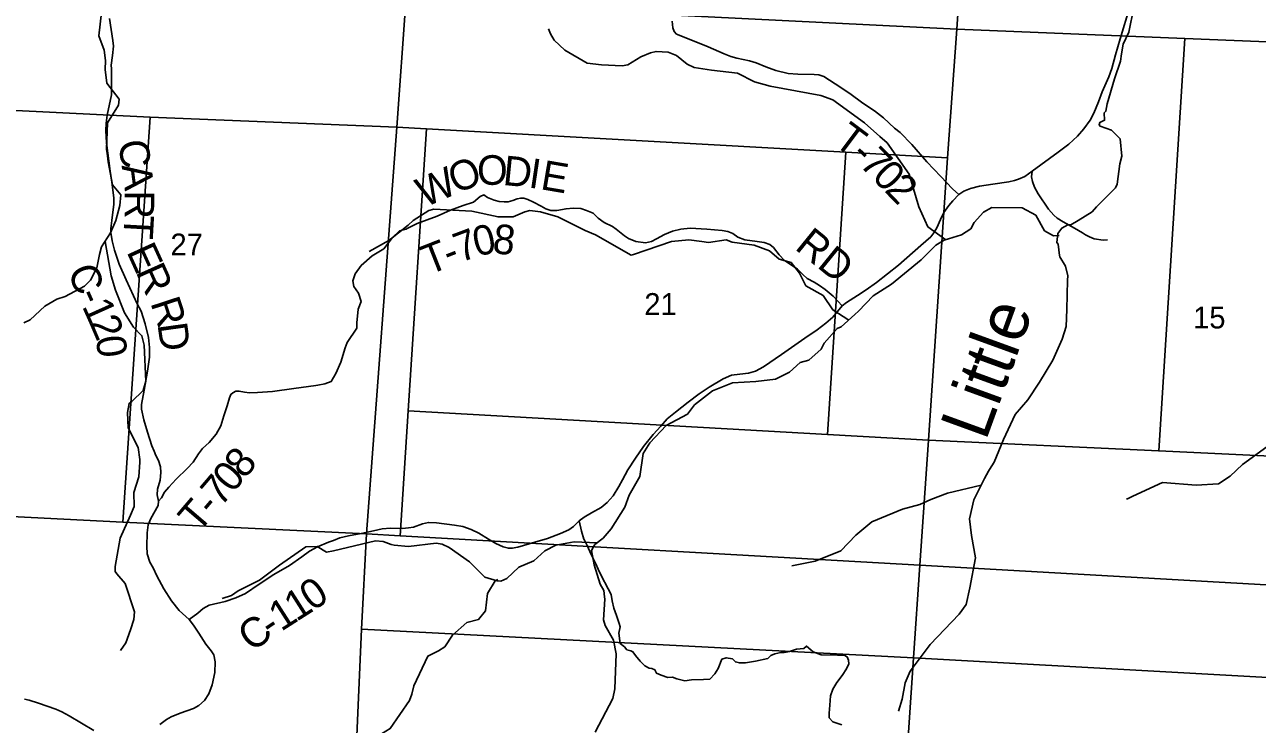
# Model space of a CAD drawing. Extents: x 1878108 to 2183446, y 146837 to 508383.
# Drawn here: x 2017962 to 2030457, y 254185 to 261280 of the extents above; entities that cross this region are included whole.
import ezdxf

# ---------------------------------------------------------------- set-up
doc = ezdxf.new("R2010")
doc.units = 0
for name, color, linetype in [('GM_X_County_Road', 7, 'Continuous'), ('GM_X_County_Road_Text', 7, 'Continuous'), ('GM_X_Minor_River', 7, 'Continuous'), ('GM_X_Minor_River_Text', 7, 'Continuous'), ('GM_X_Section', 7, 'Continuous'), ('GM_X_Section_Text', 7, 'Continuous'), ('GM_X_Township_Road', 7, 'Continuous'), ('GM_X_Township_Road_Text', 7, 'Continuous'), ('GM_X_Township_ROW', 7, 'Continuous')]:
    doc.layers.add(name, color=color, linetype=linetype)

msp = doc.modelspace()

# ---------------------------------------------------------------- linework, layer by layer
at = {"layer": 'GM_X_County_Road'}
for points in [[(2027431, 259557), (2027481, 259593), (2027548, 259620), (2027639, 259642), (2027777, 259663), (2027936, 259686), (2027994, 259701), (2028036, 259713), (2028099, 259742), (2028174, 259795), (2028436, 259986), (2028546, 260069), (2028634, 260149), (2028697, 260225), (2028762, 260313), (2028800, 260383), (2028845, 260499), (2028884, 260599), (2028950, 260750), (2028980, 260837), (2029018, 260973), (2029067, 261136), (2029165, 261460)], [(2019628, 255247), (2019527, 255340), (2019450, 255438), (2019373, 255561), (2019303, 255690), (2019265, 255772), (2019230, 255830), (2019204, 255916), (2019201, 255991), (2019203, 256128), (2019214, 256207), (2019242, 256272), (2019316, 256404), (2019320, 256449), (2019306, 256514), (2019309, 256569), (2019334, 256660), (2019341, 256739), (2019339, 256796), (2019319, 256860), (2019293, 256910), (2019274, 256955), (2019252, 257008), (2019208, 257148), (2019169, 257272), (2019148, 257381), (2019145, 257428), (2019173, 257573), (2019208, 257768), (2019228, 257908), (2019227, 258006), (2019217, 258109), (2019184, 258248), (2019143, 258376), (2019102, 258449), (2019066, 258531), (2018991, 258692), (2018920, 258853), (2018872, 258992), (2018848, 259089), (2018836, 259173), (2018837, 259214), (2018845, 259293), (2018866, 259460), (2018866, 259525), (2018845, 259683), (2018830, 259796), (2018791, 260082), (2018784, 260208), (2018789, 260283), (2018800, 260362), (2018844, 260570), (2018841, 260669), (2018842, 260783), (2018841, 260832), (2018839, 260871), (2018854, 260968), (2018861, 261062), (2018856, 261121), (2018822, 261342)], [(2021092, 256051), (2021157, 256075), (2021245, 256096), (2021372, 256121), (2021497, 256146), (2021586, 256167), (2021669, 256175), (2021792, 256172), (2021853, 256177), (2021904, 256184), (2021995, 256219), (2022054, 256233), (2022135, 256228), (2022318, 256205), (2022404, 256190), (2022489, 256162), (2022567, 256125), (2022663, 256062), (2022739, 256018), (2022811, 255984), (2022865, 255971), (2022905, 255971), (2022962, 255982), (2023132, 256032), (2023263, 256070), (2023394, 256121), (2023478, 256157), (2023525, 256190), (2023581, 256248), (2023634, 256287), (2023708, 256329), (2023807, 256384), (2023867, 256434), (2023926, 256504), (2023985, 256596), (2024023, 256665), (2024077, 256767), (2024152, 256885), (2024235, 257002), (2024333, 257123), (2024409, 257209), (2024475, 257282), (2024558, 257352), (2024686, 257451), (2024800, 257538), (2024900, 257606), (2025042, 257690), (2025126, 257726), (2025210, 257736), (2025300, 257747), (2025371, 257768), (2025450, 257810), (2025634, 257937), (2025869, 258102), (2025994, 258185), (2026083, 258254), (2026153, 258315), (2026247, 258428), (2026292, 258464), (2026405, 258535), (2026492, 258591), (2026597, 258666), (2026820, 258843), (2027047, 259042), (2027146, 259128), (2027178, 259168), (2027208, 259220), (2027244, 259305), (2027280, 259377), (2027329, 259448), (2027369, 259494), (2027431, 259557)], [(2019331, 254184), (2019399, 254235), (2019447, 254263), (2019539, 254300), (2019672, 254346), (2019726, 254376), (2019785, 254427), (2019829, 254496), (2019863, 254587), (2019891, 254710), (2019893, 254819), (2019880, 254889), (2019852, 254932), (2019800, 254998), (2019729, 255111), (2019672, 255192), (2019628, 255247), (2019716, 255312), (2019773, 255360), (2019832, 255393), (2019995, 255432), (2020102, 255468), (2020200, 255513), (2020338, 255606), (2020489, 255705), (2020646, 255795), (2020773, 255885), (2020848, 255941), (2020930, 255984), (2021043, 256033), (2021092, 256051)], [(2017960, 254442), (2018009, 254432), (2018101, 254401), (2018279, 254339), (2018339, 254313), (2018413, 254273), (2018537, 254198), (2018662, 254124)]]:
    msp.add_lwpolyline(points, dxfattribs=at)
at = {"layer": 'GM_X_Minor_River'}
for points in [[(2018742, 261403), (2018713, 261167), (2018769, 261023), (2018781, 260916), (2018777, 260824), (2018796, 260687), (2018921, 260525), (2018913, 260463), (2018802, 260284), (2018790, 260018), (2018802, 259949), (2018808, 259889), (2018851, 259655), (2018938, 259556), (2018928, 259446), (2018886, 259295), (2018832, 259170), (2018742, 259027), (2018722, 258949), (2018694, 258814), (2018630, 258689), (2018568, 258627), (2018372, 258523), (2018289, 258498), (2018167, 258425), (2018019, 258286), (2017954, 258256)], [(2029205, 261456), (2029155, 261205), (2029095, 261084), (2029079, 260984), (2029070, 260909), (2029010, 260731), (2028934, 260476), (2028922, 260403), (2028904, 260385), (2028908, 260311), (2028859, 260287), (2028853, 260265), (2028863, 260251), (2028978, 260209), (2029066, 260121), (2029084, 259948), (2029063, 259868), (2029037, 259663), (2029019, 259625), (2028827, 259434), (2028782, 259383), (2028640, 259293), (2028566, 259250), (2028534, 259252), (2028474, 259218), (2028435, 259162), (2028423, 259071), (2028439, 259053), (2028451, 258939), (2028455, 258925), (2028511, 258831), (2028535, 258732), (2028531, 258688), (2028527, 258391), (2028519, 258219), (2028479, 258092), (2028382, 257877), (2028250, 257654), (2028129, 257477), (2028003, 257328), (2027882, 257073), (2027788, 256844), (2027740, 256768), (2027730, 256752), (2027690, 256679), (2027582, 256462)], [(2027299, 259100), (2027118, 259231), (2027025, 259433), (2026999, 259524), (2026927, 259765), (2026705, 260081), (2026631, 260145), (2026476, 260285), (2026153, 260519), (2026031, 260563), (2025517, 260656), (2025361, 260701), (2025188, 260787), (2024925, 260819), (2024748, 260847), (2024678, 260881), (2024570, 260969), (2024484, 261002), (2024362, 261009), (2024304, 260995), (2024207, 260954), (2024077, 260872), (2024018, 260862), (2023809, 260873), (2023662, 260889), (2023437, 261023), (2023328, 261123), (2023292, 261188), (2023271, 261239)], [(2026315, 258285), (2026153, 258388), (2026057, 258533), (2025881, 258633), (2025852, 258686), (2025817, 258760), (2025730, 258867), (2025611, 258902), (2025512, 258988), (2025356, 259043), (2025132, 259074), (2025071, 259098), (2024894, 259072), (2024825, 259080), (2024693, 259100), (2024517, 259082), (2024134, 258951), (2024108, 258942), (2023749, 259150), (2023645, 259194), (2023365, 259331), (2023191, 259384), (2023084, 259396), (2023032, 259383), (2022912, 259331), (2022761, 259330), (2022493, 259389), (2022110, 259409), (2022060, 259396), (2021901, 259293), (2021850, 259247), (2021654, 259090), (2021453, 258979)], [(2028449, 259143), (2028391, 259139), (2028298, 259190), (2028211, 259347), (2028072, 259422), (2027765, 259425), (2027682, 259380), (2027586, 259273), (2027551, 259210), (2027457, 259150), (2027282, 259094), (2027198, 259044), (2027050, 258897), (2026749, 258648), (2026564, 258531), (2026414, 258374), (2026377, 258341), (2026237, 258215), (2026197, 258198), (2026067, 258050), (2026035, 257991), (2025910, 257878), (2025823, 257853), (2025713, 257758), (2025573, 257687), (2025374, 257663), (2025136, 257648), (2024934, 257568), (2024750, 257424), (2024682, 257332), (2024463, 257217), (2024298, 257041), (2024283, 257014), (2024231, 256933), (2024196, 256700), (2024088, 256509), (2024047, 256388), (2023906, 256167), (2023826, 256074), (2023742, 256008), (2023706, 255949), (2023735, 255802), (2023795, 255606), (2023831, 255544), (2023841, 255480), (2023843, 255454), (2023828, 255246), (2023845, 255189), (2023932, 255038), (2023958, 254899), (2023945, 254544), (2023924, 254446), (2023744, 254107)], [(2018777, 259083), (2018839, 258733), (2018884, 258587), (2018975, 258358), (2019067, 258214), (2019150, 258125), (2019175, 258030), (2019190, 257665), (2019163, 257572), (2019050, 257459), (2019021, 257440), (2019004, 257346), (2019012, 257193), (2019114, 256994), (2019130, 256871), (2019131, 256843), (2019118, 256695), (2019068, 256538), (2019071, 256396), (2019035, 256308), (2018930, 256073), (2018881, 255786), (2018878, 255736), (2018897, 255711), (2018982, 255614), (2019075, 255327), (2019069, 255249), (2019034, 255144), (2018988, 255011), (2018933, 254934)], [(2033231, 257131), (2032756, 257108), (2032464, 257002), (2032332, 256997), (2032035, 257096), (2031862, 257197), (2031655, 257280), (2031478, 257322), (2031338, 257333), (2031001, 257303), (2030838, 257204), (2030305, 256820), (2030182, 256703), (2030064, 256623), (2029838, 256611), (2029495, 256638), (2029195, 256500), (2029139, 256473), (2029129, 256471)], [(2027656, 256610), (2027316, 256530), (2027148, 256465), (2027037, 256415), (2026860, 256368), (2026549, 256238), (2026387, 256103), (2026236, 255945), (2025974, 255841), (2025737, 255794)], [(2027582, 256463), (2027540, 256270), (2027558, 256101), (2027601, 255875), (2027544, 255568), (2027505, 255401), (2027434, 255303), (2027140, 254996), (2026938, 254723), (2026888, 254607), (2026858, 254441), (2026820, 254318)], [(2023765, 256027), (2023533, 256035), (2023346, 256003), (2023235, 255946), (2023124, 255843), (2022970, 255778), (2022851, 255664), (2022787, 255638), (2022751, 255641), (2022628, 255679), (2022471, 255834), (2022266, 255977), (2022193, 256013), (2022132, 256023), (2021853, 255990), (2021708, 256003), (2021678, 256010), (2021597, 256040), (2021518, 256045), (2021091, 255944), (2021021, 255932), (2020927, 255990), (2020813, 255985), (2020546, 255801), (2020344, 255647), (2020125, 255540), (2020060, 255492), (2019963, 255461)], [(2022757, 255655), (2022731, 255641), (2022655, 255513), (2022634, 255336), (2022563, 255250), (2022443, 255217), (2022297, 255090), (2022220, 254970), (2022158, 254930), (2022047, 254877), (2021906, 254577), (2021886, 254493), (2021862, 254426), (2021668, 254143), (2021580, 254090), (2021474, 254077), (2021448, 254074), (2021308, 254054), (2021173, 254007), (2021083, 253933), (2020916, 253838), (2020784, 253746), (2020680, 253609)]]:
    msp.add_lwpolyline(points, dxfattribs=at)
at = {"layer": 'GM_X_Section'}
for points in [[(2027727, 266517), (2033229, 266210), (2033091, 264128), (2032945, 261923), (2032890, 261012), (2029722, 261139), (2027410, 261234), (2027470, 262145), (2027599, 264349)], [(2021897, 262418), (2027470, 262145), (2027410, 261234), (2021824, 261513)], [(2016468, 261780), (2021824, 261513), (2021735, 260242), (2019234, 260342), (2016374, 260485)], [(2021824, 261513), (2027410, 261234), (2027316, 259930), (2026284, 259988), (2022035, 260225), (2021735, 260242)], [(2029722, 261139), (2029458, 256958), (2027123, 257067), (2027316, 259930), (2027410, 261234)], [(2032890, 261012), (2032820, 259673), (2032478, 259688), (2032295, 256825), (2029458, 256958), (2029722, 261139)], [(2019234, 260342), (2018956, 256236), (2016099, 256382), (2016374, 260485)], [(2021735, 260242), (2021428, 256117), (2018956, 256236), (2019234, 260342)], [(2021735, 260242), (2022035, 260225), (2021850, 257366), (2021768, 256098), (2021428, 256117)], [(2022035, 260225), (2026284, 259988), (2026098, 257125), (2021850, 257366)], [(2026284, 259988), (2027316, 259930), (2027123, 257067), (2026098, 257125)], [(2026098, 257125), (2027123, 257067), (2027037, 255799), (2021768, 256098), (2021850, 257366)], [(2029458, 256958), (2032295, 256825), (2032211, 255505), (2027037, 255799), (2027123, 257067)], [(2018956, 256236), (2021428, 256117), (2021376, 255152), (2021283, 252989), (2021200, 250855), (2015798, 251134), (2016099, 256382)], [(2021768, 256098), (2027037, 255799), (2026973, 254859), (2021376, 255152), (2021428, 256117)], [(2032211, 255505), (2032559, 255485), (2032511, 254552), (2026973, 254859), (2027037, 255799)], [(2026973, 254859), (2026826, 252691), (2021283, 252989), (2021376, 255152)], [(2032511, 254552), (2032382, 252416), (2026826, 252691), (2026973, 254859)]]:
    msp.add_lwpolyline(points, close=True, dxfattribs=at)
at = {"layer": 'GM_X_Township_Road'}
for points in [[(2027431, 259557), (2027368, 259616), (2027250, 259739), (2027107, 259889), (2026953, 260064), (2026835, 260188), (2026778, 260230), (2026666, 260337), (2026577, 260408), (2026459, 260485), (2026326, 260582), (2026178, 260680), (2026063, 260755), (2026011, 260771), (2025963, 260774), (2025800, 260779), (2025701, 260786), (2025577, 260816), (2025476, 260854), (2025378, 260894), (2025310, 260915), (2025180, 260942), (2025121, 260958), (2025052, 260986), (2024891, 261057), (2024680, 261139), (2024570, 261184), (2024546, 261211), (2024531, 261247), (2024525, 261315)], [(2028174, 259795), (2028168, 259737), (2028177, 259689), (2028197, 259633), (2028236, 259566), (2028341, 259409), (2028393, 259347), (2028429, 259317), (2028487, 259281), (2028602, 259216), (2028683, 259169)], [(2021839, 259212), (2021939, 259263), (2022143, 259338), (2022277, 259399), (2022407, 259448), (2022513, 259479), (2022579, 259537), (2022617, 259554), (2022652, 259528), (2022722, 259499), (2022773, 259488), (2022824, 259484), (2022862, 259484), (2022910, 259497), (2022955, 259514), (2022991, 259521), (2023023, 259521), (2023061, 259507), (2023119, 259480), (2023196, 259441), (2023245, 259412), (2023297, 259395), (2023355, 259396), (2023450, 259414), (2023523, 259419), (2023601, 259415), (2023658, 259397), (2023723, 259368), (2023776, 259319), (2023837, 259275), (2023919, 259233), (2023959, 259205), (2024042, 259138), (2024084, 259111), (2024158, 259080), (2024254, 259067), (2024315, 259081), (2024365, 259108), (2024449, 259153), (2024530, 259186), (2024614, 259206), (2024706, 259218), (2024876, 259207), (2025031, 259194), (2025090, 259183), (2025140, 259164), (2025192, 259127), (2025263, 259100), (2025386, 259080), (2025458, 259070), (2025514, 259051), (2025553, 259020), (2025610, 258945), (2025665, 258890), (2025741, 258839), (2025795, 258801), (2025848, 258746), (2025894, 258706), (2025965, 258668), (2026019, 258637), (2026076, 258595), (2026157, 258528), (2026206, 258477), (2026247, 258428)], [(2019320, 256449), (2019348, 256482), (2019378, 256540), (2019422, 256592), (2019497, 256670), (2019610, 256781), (2019671, 256845), (2019725, 256928), (2019764, 256982), (2019832, 257043), (2019903, 257128), (2019951, 257213), (2019980, 257315), (2020015, 257415), (2020037, 257497), (2020053, 257531), (2020071, 257548), (2020101, 257563), (2020136, 257563), (2020190, 257555), (2020242, 257548), (2020321, 257550), (2020474, 257560), (2020690, 257590), (2020915, 257623), (2020934, 257626)], [(2023581, 256248), (2023607, 256145), (2023631, 256062), (2023636, 256052)]]:
    msp.add_lwpolyline(points, dxfattribs=at)
at = {"layer": 'GM_X_Township_ROW'}
for points in [[(2020934, 257626), (2021005, 257639), (2021069, 257662), (2021115, 257742), (2021168, 257859), (2021210, 258004), (2021230, 258059), (2021328, 258204), (2021329, 258257), (2021344, 258397), (2021372, 258474), (2021346, 258558), (2021297, 258625), (2021287, 258681), (2021313, 258753), (2021372, 258838), (2021484, 258937), (2021602, 259006), (2021692, 259123), (2021761, 259188), (2021830, 259207), (2021839, 259212)], [(2028683, 259169), (2028716, 259150), (2028754, 259130), (2028804, 259107), (2028895, 259094), (2028939, 259099)], [(2023636, 256052), (2023662, 255999), (2023705, 255906), (2023750, 255812), (2023776, 255759), (2023806, 255695), (2023875, 255559), (2023907, 255503), (2023917, 255439), (2023933, 255364), (2023962, 255290), (2023987, 255209), (2023999, 255175), (2023985, 255110), (2023999, 255005), (2024041, 254971), (2024067, 254941), (2024107, 254930), (2024128, 254922), (2024153, 254885), (2024200, 254825), (2024249, 254780), (2024291, 254755), (2024318, 254753), (2024350, 254738), (2024365, 254705), (2024413, 254683), (2024482, 254659), (2024529, 254664), (2024574, 254648), (2024655, 254626), (2024721, 254636), (2024843, 254640), (2024908, 254645), (2024959, 254697), (2024990, 254752), (2025029, 254846), (2025073, 254861), (2025136, 254849), (2025166, 254819), (2025206, 254808), (2025267, 254808), (2025369, 254826), (2025496, 254854), (2025526, 254882), (2025566, 254901), (2025627, 254915), (2025662, 254915), (2025679, 254918), (2025715, 254925), (2025786, 254948), (2025859, 254954), (2025888, 254979), (2025956, 254920), (2026034, 254889), (2026200, 254887), (2026267, 254886), (2026298, 254869), (2026314, 254835), (2026315, 254798), (2026293, 254749), (2026249, 254679), (2026195, 254610), (2026154, 254543), (2026131, 254476), (2026124, 254381), (2026116, 254298), (2026116, 254252), (2026155, 254212), (2026245, 254182)]]:
    msp.add_lwpolyline(points, dxfattribs=at)

# ---------------------------------------------------------------- texts
at = {"layer": 'GM_X_County_Road_Text'}
for s, rotation, p in [('C', 277.6924, (2018911, 260096)), ('A', 277.4707, (2018944, 259852)), ('R', 269.4223, (2018977, 259601)), ('T', 266.8141, (2018975, 259358)), ('E', 294.5102, (2018991, 258980)), ('C', 290.8671, (2018395, 258787)), ('R', 294.1713, (2019084, 258776)), ('-', 294.1, (2018490, 258540)), ('R', 288.1418, (2019235, 258461)), ('1', 294.1433, (2018540, 258427)), ('2', 293.0964, (2018615, 258260)), ('D', 277.9042, (2019308, 258241)), ('0', 277.2845, (2018682, 258111)), ('0', 34.2863, (2020881, 255327)), ('1', 32.4848, (2020716, 255222)), ('1', 32.6227, (2020561, 255122)), ('C', 35.809, (2020263, 254912)), ('-', 34.1415, (2020461, 255054))]:
    msp.add_text(s, height=300, rotation=rotation, dxfattribs=at).set_placement(p)
at = {"layer": 'GM_X_Minor_River_Text'}
msp.add_text('Little ', height=500, rotation=70.0041, dxfattribs=at).set_placement((2027703, 257050))
at = {"layer": 'GM_X_Section_Text'}
for s, p in [('27', (2019440, 258941)), ('21', (2024243, 258337)), ('15', (2029805, 258200))]:
    msp.add_text(s, height=221, rotation=0, dxfattribs=at).set_placement(p)
at = {"layer": 'GM_X_Township_Road_Text'}
for s, rotation, p in [('T', 323.1138, (2026150, 260071)), ('-', 317.0427, (2026323, 259942)), ('7', 314.4793, (2026411, 259860)), ('O', 22.7387, (2022333, 259561)), ('O', 359.7887, (2022546, 259657)), ('D', 354.3043, (2022802, 259656)), ('I', 351.5785, (2023061, 259631)), ('E', 350.3918, (2023181, 259613)), ('0', 314.1776, (2026540, 259729)), ('W', 23.5472, (2022016, 259423)), ('2', 314.1223, (2026668, 259596)), ('8', 353.3894, (2022695, 258966)), ('7', 20.4044, (2022378, 258865)), ('0', 12.6919, (2022541, 258927)), ('RD', 320.9542, (2025758, 259010)), ('T', 21.4409, (2022056, 258739)), ('-', 21.255, (2022264, 258821)), ('8', 50.2182, (2020190, 256665)), ('0', 49.7228, (2020069, 256522)), ('7', 49.5559, (2019949, 256381)), ('T', 49.4986, (2019723, 256116)), ('-', 49.5025, (2019868, 256287))]:
    msp.add_text(s, height=300, rotation=rotation, dxfattribs=at).set_placement(p)

doc.saveas('drawing.dxf')
